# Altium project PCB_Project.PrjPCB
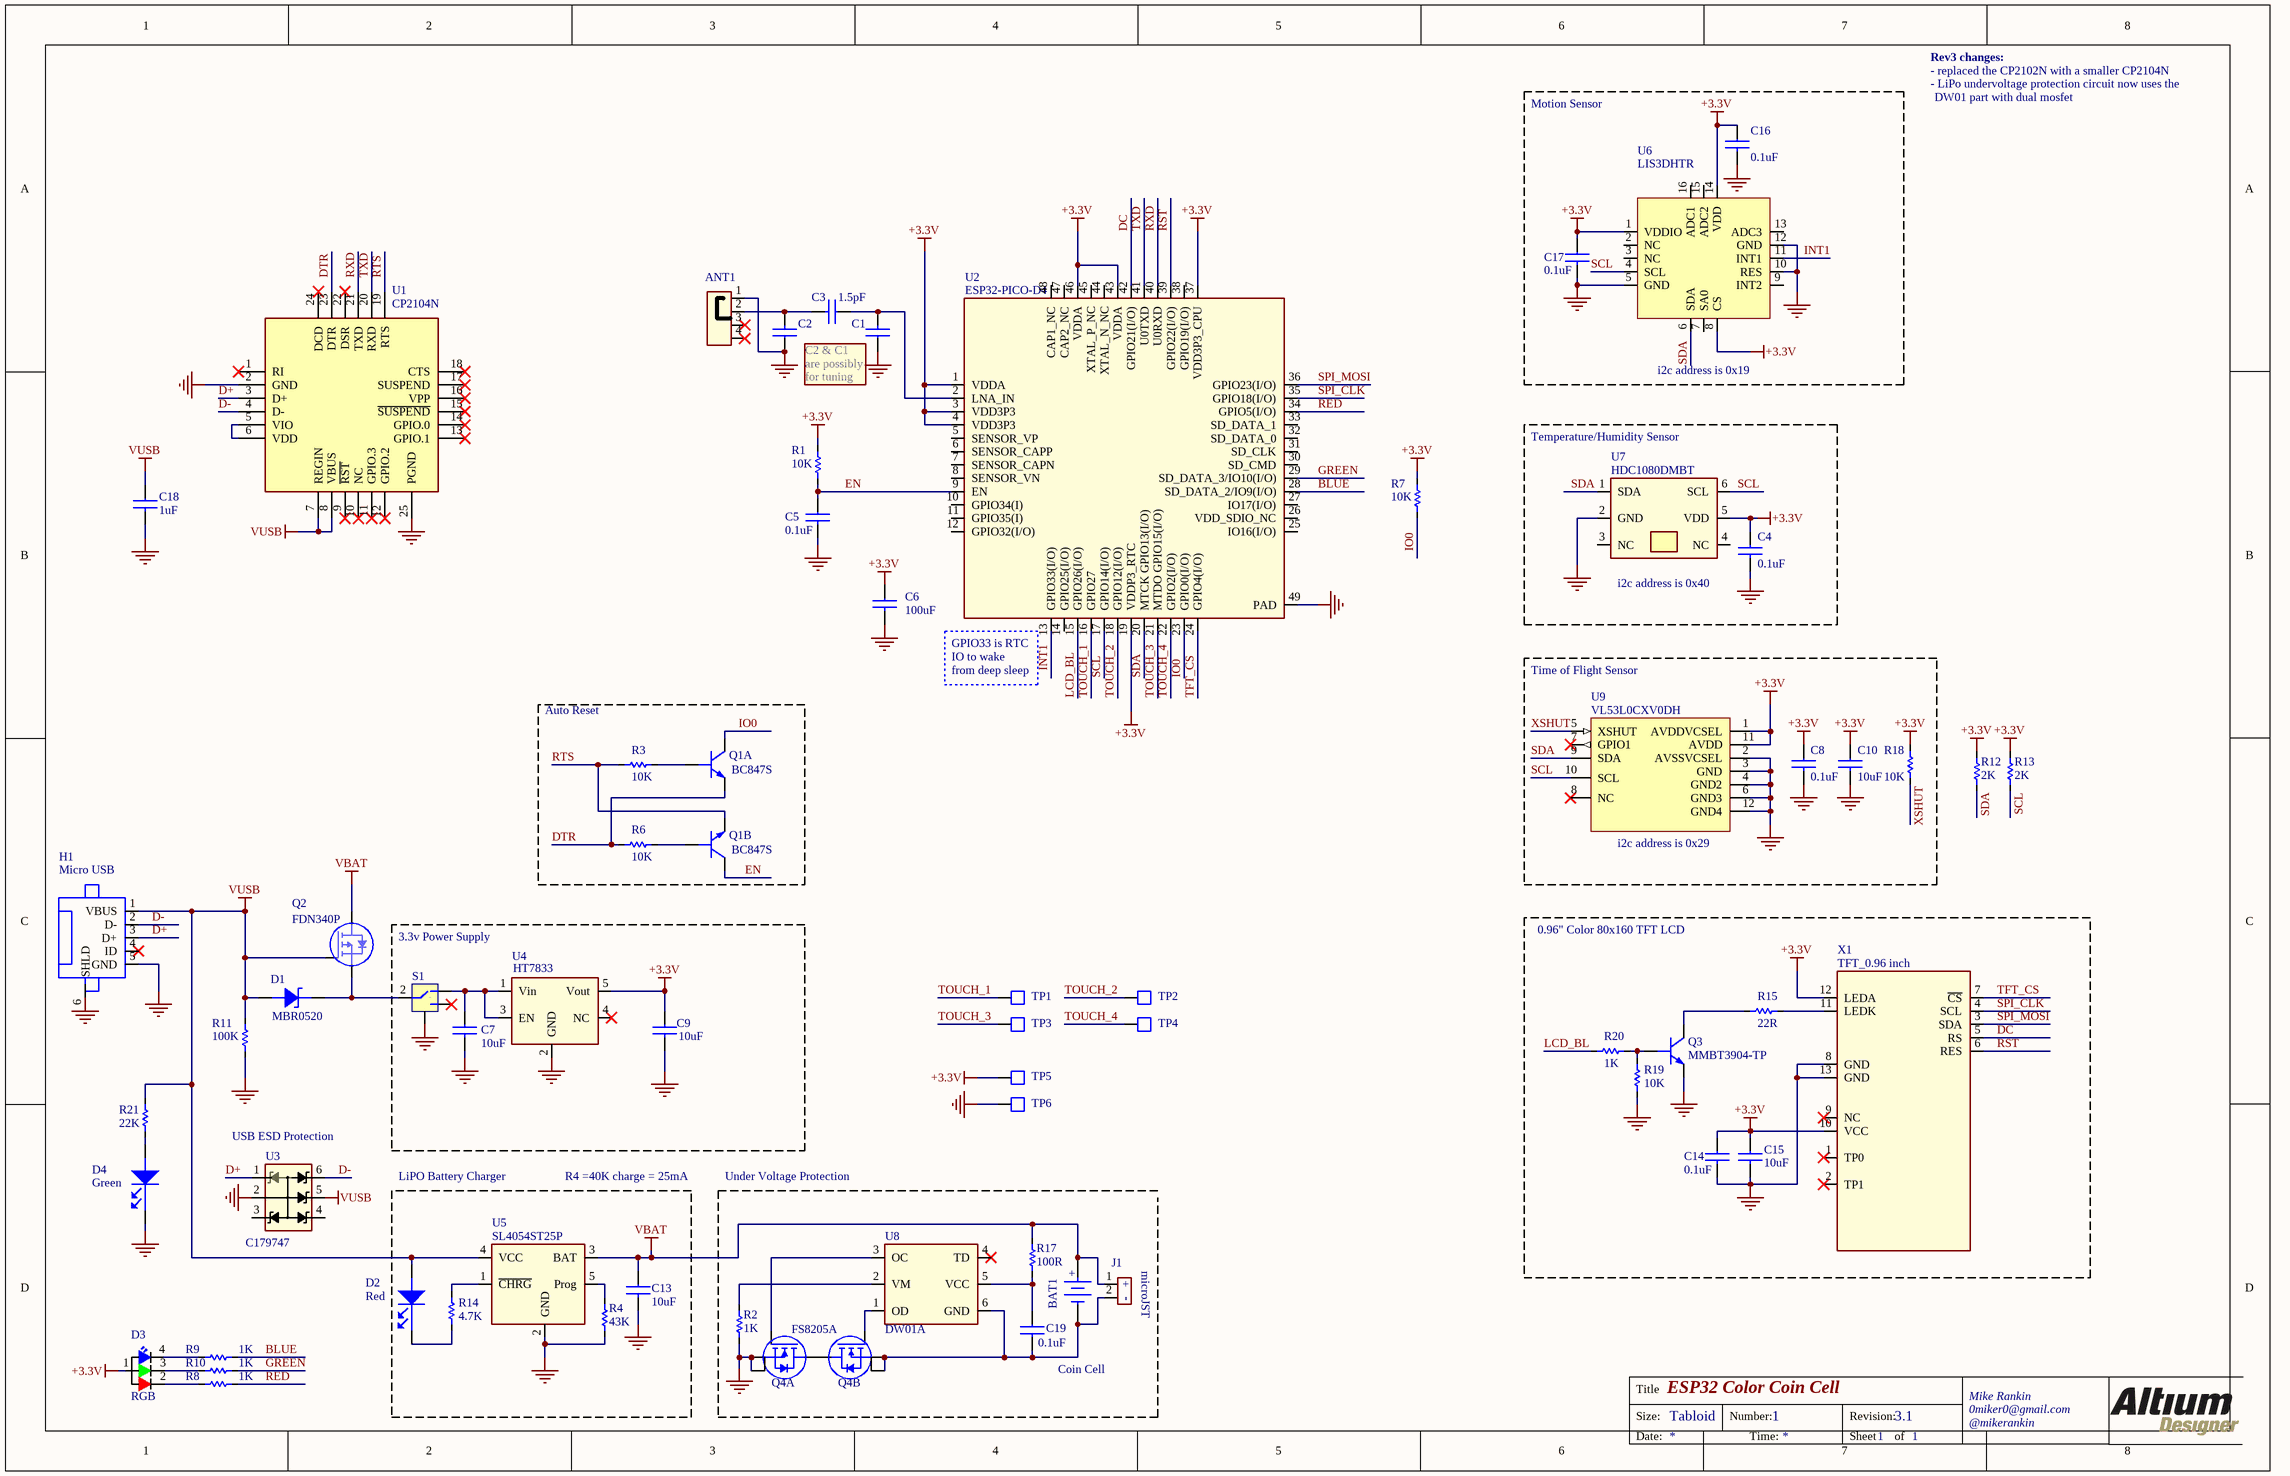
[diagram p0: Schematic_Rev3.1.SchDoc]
1 sheet, 65 parts. Net scope: global (net labels, ports and power ports of the same name join across sheets).
Board file: PCB_Rev3.1.PcbDoc

## Sheet Schematic_Rev3.1.SchDoc: ESP32 Color Coin Cell
size Tabloid; DrawnBy: x; Engineer: x; Address1: Mike Rankin; Address2: 0miker0@gmail.com; Address3: @mikerankin; DocumentNumber: 1; Revision: 3.1; SheetNumber: 1; SheetTotal: 1

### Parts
ANT1  RF ANT 2.4GHZ STAMPED MET SLD  [PRO-OB-440]  (value not drawn)
BAT1  BATTERY-HOLDER (2450)  [BU2450SM-JJ-GTR]  (value not drawn)
C1  (no value)  [CAPC1005X56N]  (no BOM)
C2  (no value)  [CAPC1005X56N]  (no BOM)
C3  1.5pF  [CAPC1005X56N]
C4  0.1uF  [CAPC1005X56N]
C5  0.1uF  [CAPC1005X56N]
C6  100uF  [CAPC3216X160L]
C7  10uF  [CAPC2012X140N]
C8  0.1uF  [CAPC1005X56N]
C9  10uF  [CAPC2012X140N]
C10  10uF  [CAPC2012X140N]
C13  10uF  [CAPC2012X140N]
C14  0.1uF  [CAPC1005X56N]
C15  10uF  [CAPC2012X140N]
C16  0.1uF  [RESC1005X40L]
C17  0.1uF  [CAPC1005X56N]
C18  1uF  [CAPC1005X56N]
C19  0.1uF  [CAPC1005X56N]
D1  MBR0520  [SOD123]
D2  value Red  [LED1608X55N-RED]  (hidden comment: LED_0603)
D3  RGB  [FC-B1010RGBT-HG]
D4  value Green  [LED1608X55N-GREEN]  (hidden comment: LED_0603)
H1  Micro USB  [1981584-1]
J1  CON2  [JST_Micro_2PIN]  (value not drawn)  (no BOM)
Q1  BC847S  [SOT65P210X110-6N]  (parts A,B of 2)
Q2  FDN340P  [SOT95P240X110-3N]
Q3  MMBT3904-TP  [SOT95P240X110-3N]
Q4  FS8205A  [TSOP65P490X110-8N WIDE]  (value not drawn)  (parts A,B of 2)
R1  10K  [RESC1005X40L]
R2  1K  [RESC1005X40L]
R3  10K  [RESC1005X40L]
R4  43K  [RESC1005X40L]
R6  10K  [RESC1005X40L]
R7  10K  [RESC1005X40L]
R8  1K  [RESC1005X40L]
R9  1K  [RESC1005X40L]
R10  1K  [RESC1005X40L]
R11  100K  [RESC1005X40L]
R12  2K  [RESC1005X40L]
R13  2K  [RESC1005X40L]
R14  4.7K  [RESC1005X40L]
R15  22R  [RESC1005X40L]
R17  100R  [RESC1005X40L]
R18  10K  [RESC1005X40L]
R19  10K  [RESC1005X40L]
R20  1K  [RESC1005X40L]
R21  22K  [RESC1005X40L]
S1  SWITCH SLIDE  [K3-1296S-E1]  (value not drawn)
TP1  Test Point, 1mm Top Layer  [TP100TL]  (value not drawn)  (no BOM)
TP2  Test Point, 1mm Top Layer  [TP100TL]  (value not drawn)  (no BOM)
TP3  Test Point, 1mm Top Layer  [TP100TL]  (value not drawn)  (no BOM)
TP4  Test Point, 1mm Top Layer  [TP100TL]  (value not drawn)  (no BOM)
TP5  Test Point, 1mm Top Layer  [TP100TL]  (value not drawn)  (no BOM)
TP6  Test Point, 1mm Top Layer  [TP100TL]  (value not drawn)  (no BOM)
U1  CP2104N  [24-QFN]
U2  ESP32-PICO-D4  [QFN48]
U3  PartNumber: C179747  [SOT65P210X110-6N]  (hidden comment: PESD5V0L5UY)
U4  HT7833  [SOT95P280X144-5N]
U5  SL4054ST25P  [SOT95P280X144-5N]
U6  LIS3DHTR  [QFN3X3_16_1.2]
U7  HDC1080DMBT  [HDC1080]
U8  DW01A  [SOT95P280X130-6N]
U9  VL53L0CXV0DH  [VL53L0CXV0DH]
X1  TFT_0.96 inch  [TFT_GLASS 0.96 INCH]

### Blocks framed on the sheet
Auto Reset: Q1 R3 R6
3.3v Power Supply: C7 C9 S1 U4
0.96" Color 80x160 TFT LCD: C14 C15 Q3 R15 R19 R20 X1

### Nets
+3.3V: C4.1 C6.1 C8.1 C9.1 C10.1 C14.1 C15.1 C16.1 C17.1 D3.1 R1.1 R7.1 R12.2 R13.2 R18.1 TP5.1 U2.1(VDDA) U2.3(VDD3P3) U2.4(VDD3P3) U2.19(VDDP3_RTC) U2.37(VDD3P3_CPU) U2.43(VDDA) U2.46(VDDA) U4.5(Vout) U6.1(VDDIO) U6.8(CS) U6.14(VDD) U7.5(VDD) U9.1(AVDDVCSEL) U9.11(AVDD) X1.10(VCC) X1.12(LEDA)
GND: ANT1.1 C1.1 C2.1 C4.2 C5.2 C6.2 C7.2 C8.2 C9.2 C10.2 C13.2 C14.2 C15.2 C16.2 C17.2 C18.2 D4.1(CATHODE) H1.5(GND) H1.6(SHLD) Q3.2(E) Q4.2(S) Q4.3(S) R2.1 R4.2 R11.2 R19.2 S1.4 TP6.1 U1.2(GND) U1.25(PGND) U2.49(PAD) U3.2 U4.2(GND) U5.2(GND) U6.5(GND) U6.10(RES) U6.12(GND) U7.2(GND) U9.2(AVSSVCSEL) U9.3(GND) U9.4(GND2) U9.6(GND3) U9.12(GND4) X1.8(GND) X1.13(GND)
VBAT: BAT1.1(+) C13.1 J1.1 Q2.3(D) R17.2 U5.3(BAT)
VUSB: C18.1 D1.2(Annode) D2.2(ANODE) H1.1(VBUS) Q2.1(G) R11.1 R21.2 U1.7(REGIN) U1.8(VBUS) U3.5 U5.4(VCC)
BLUE: R9.2 U2.28(SD_DATA_2/IO9(I/O))
D+: H1.3(D+) U1.3(D+) U3.1
D-: H1.2(D-) U1.4(D-) U3.6
DC: U2.42(GPIO21(I/O)) X1.5(RS)
DTR: Q1.1(E1) R6.2 U1.23(DTR)
EN: C5.1 Q1.3(C2) R1.2 U2.9(EN)
GREEN: R10.2 U2.29(SD_DATA_3/IO10(I/O))
INT1: U2.13(GPIO33(I/O)) U6.11(INT1)
IO0: Q1.6(C1) R7.2 U2.23(GPIO0(I/O))
LCD_BL: R20.1 U2.15(GPIO26(I/O))
RED: R8.2 U2.34(GPIO5(I/O))
RST: U2.39(GPIO22(I/O)) X1.6(RES)
RTS: Q1.4(E2) R3.2 U1.19(RTS)
RXD: U1.21(TXD) U2.40(U0RXD)
SCL: R13.1 U2.17(GPIO14(I/O)) U6.4(SCL) U7.6(SCL) U9.10(SCL)
SDA: R12.1 U2.20(MTCK_GPIO13(I/O)) U6.6(SDA) U7.1(SDA) U9.9(SDA)
SPI_CLK: U2.35(GPIO18(I/O)) X1.4(SCL)
SPI_MOSI: U2.36(GPIO23(I/O)) X1.3(SDA)
TFT_CS: U2.24(GPIO4(I/O)) X1.7(~{CS})
TOUCH_1: TP1.1 U2.16(GPIO27)
TOUCH_2: TP2.1 U2.18(GPIO12(I/O))
TOUCH_3: TP3.1 U2.21(MTDO_GPIO15(I/O))
TOUCH_4: TP4.1 U2.22(GPIO2(I/O))
TXD: U1.20(RXD) U2.41(U0TXD)
XSHUT: R18.2 U9.5(XSHUT)
NetANT1_2: ANT1.2 C2.2 C3.2
NetBAT1_2: BAT1.2(-) C19.2 J1.2 Q4.6(S) Q4.7(S) U8.6(GND)
NetC1_2: C1.2 C3.1 U2.2(LNA_IN)
NetC7_1: C7.1 S1.1 U4.1(Vin) U4.3(EN)
NetC19_1: C19.1 R17.1 U8.5(VCC)
NetD1_1: D1.1(Cathode) Q2.2(S) S1.2
NetD2_1: D2.1(CATHODE) R14.1
NetD3_2: D3.2 R8.1
NetD3_3: D3.3 R10.1
NetD3_4: D3.4 R9.1
NetD4_2: D4.2(ANODE) R21.1
NetQ1_2: Q1.2(B1) R3.1
NetQ1_5: Q1.5(B2) R6.1
NetQ3_1: Q3.1(B) R19.1 R20.2
NetQ3_3: Q3.3(C) R15.2
NetQ4_1: Q4.1(D) Q4.8(D)
NetQ4_4: Q4.4(G) U8.3(OC)
NetQ4_5: Q4.5(G) U8.1(OD)
NetR2_2: R2.2 U8.2(VM)
NetR4_1: R4.1 U5.5(Prog)
NetR14_2: R14.2 U5.1(~{CHRG})
NetR15_1: R15.1 X1.11(LEDK)
NetU1_5: U1.5(VIO) U1.6(VDD)

Not connected (* = marked no-connect by the designer): ANT1 3* 4*; H1 4(ID)*; S1 3*; U1 1(RI)* 9(~{RST})* 10(NC)* 11(GPIO.3)* 12(GPIO.2)* 13(GPIO.1)* 14(GPIO.0)* 15(~{SUSPEND})* 16(VPP)* 17(SUSPEND)* 18(CTS)* 22(DSR)* 24(DCD)*; U2 5(SENSOR_VP) 6(SENSOR_CAPP) 7(SENSOR_CAPN) 8(SENSOR_VN) 10(GPIO34(I)) 11(GPIO35(I)) 12(GPIO32(I/O)) 14(GPIO25(I/O)) 25(IO16(I/O)) 26(VDD_SDIO_NC) 27(IO17(I/O)) 30(SD_CMD) 31(SD_CLK) 32(SD_DATA_0) 33(SD_DATA_1) 38(GPIO19(I/O)) 44(XTAL_N_NC) 45(XTAL_P_NC) 47(CAP2_NC) 48(CAP1_NC); U3 3 4; U4 4(NC)*; U6 2(NC) 3(NC) 7(SA0) 9(INT2) 13(ADC3) 15(ADC2) 16(ADC1); U7 3(NC) 4(NC); U8 4(TD)*; U9 7(GPIO1)* 8(NC)*; X1 1(TP0)* 2(TP1)* 9(NC)*

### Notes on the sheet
- Rev3 changes:
- - replaced the CP2102N with a smaller CP2104N
- - LiPo undervoltage protection circuit now uses the
- Motion Sensor
- DW01 part with dual mosfet
- C2 & C1
- are possibly
- for tuning
- (near U6) i2c address is 0x19
- (near U7) Temperature/Humidity Sensor
- i2c address is 0x40
- (near U2) GPIO33 is RTC
- (near U2) IO to wake
- (near U2) from deep sleep
- Time of Flight Sensor
- (near U9) i2c address is 0x29
- (near U3) USB ESD Protection
- LiPO Battery Charger
- R4 =40K charge = 25mA
- Under Voltage Protection
- (near J1) microJST
- (near C19) Coin Cell
- Labels drawn without touching a wire or pin: ~{}

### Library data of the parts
ANT1 = PRO-OB-440: Manufacturer: Proant AB; Vendor: Digi-Key
BAT1 = BU2450SM-JJ-GTR: HOLDER,BATT,COIN,24.5MM,SMT; Manufacturer: MPD; Value: Coin Cell Holder; Vendor: Digi-Key
C1 C2 = CAP_0402: DNP
C3 = CAP_0402: CAP 1.5pF 0402; PartNumber: C147344; Manufacturer: Dafron; Part_Footprint: 0402; Vendor: LCSC
C4 C5 C8 C14 C16 C17 C19 = CAP_0402: CAP 0.1uF 0402; PartNumber: C344190; Manufacturer: CCTC; Vendor: LCSC
C6 = CAP_1206: CAP 100uF 6.3V 1206; PartNumber: C87164; Manufacturer: Taiyo Yuden; Vendor: LCSC
C7 C9 C10 C15 = CAP_0805: CAP 10uF 0805; Manufacturer: Samsung; PartNumber: C307520; Vendor: LCSC
C13 = CAP_0805: CAP 10uF 0805; PartNumber: C307520; Manufacturer: Samsung; Vendor: LCSC
C18 = CAP_0603: CAP 1uF 16V 0402; PartNumber: C83063; Manufacturer: Walsin; Vendor: LCSC
D1 = MBR0520-TP: DIODE SCHOTTKY 20V 500MA SOD123; Manufacturer: CJ; PartNumber: C475717; Vendor: LCSC
D2 = LED_0603: LED RED CLEAR 0603 SMD; Manufacturer: FNO; PartNumber: C94869; Vendor: LCSC
D3 = FC-B1010RGBT-HG: LED,RGB LED,SMD,RoHS; PartNumber: C158099; Manufacturer: Foshan; Vendor: LCSC; Value: RGB Led
D4 = LED_0603: LED Green 0603; Manufacturer: Lite-On; PartNumber: C125094; Vendor: LCSC
H1 = 1981584-1: CONN RCPT MICRO USB TYPE AB; Manufacturer: REG CON; PartNumber: C21377; Vendor: LCSC
J1 = JST_Micro_CONN_2PIN: JST MIcro CONN 2POS
Q1 = BC847S: TRANS 2NPN 44V 0.1A SC-70-6; Manufacturer: Changjiang; Vendor: LCSC
Q2 = FDN340P: MOSFET P-CH 20V 2A SOT-23; Manufacturer: On Semi; PartNumber: C75469; Vendor: LCSC; Value: Mosfet P-H
Q3 = MMBT3904-TP: TRANSISTOR NPN SOT23; Manufacturer: Micro Commercial; PartNumber: C668969; Vendor: LCSC
Q4 = FS8205A: MOSFET 2N-CH 20V 6A TSSOP-8L; Manufacturer: Fortune; PartNumber: C16052; Vendor: LCSC
R1 R3 R6 R7 R18 R19 = RES_0402: RES 10K 0402; PartNumber: C258091; Manufacturer: Guangdong; Vendor: LCSC
R2 R8-R10 R20 = RES_0402: RES 1K 0402; PartNumber: C106235; Manufacturer: Yageo; Vendor: LCSC
R4 = RES_0603: RES 43K 0402; Manufacturer: Uniroyal; PartNumber: C8329; Vendor: LCSC
R11 = RES_0603: RES 100K 0402; Manufacturer: Uniroyal Elec; PartNumber: C25741; Vendor: LCSC
R12 R13 = RES_0402: RES 2K 0402; Manufacturer: LIZ Elec; PartNumber: C100291; Vendor: LCSC
R14 = RES_0603: RES 4.7K 0402; Manufacturer: LIZ Elec; PartNumber: C100139; Vendor: LCSC
R15 = RES_0402: RES 22R 0402; PartNumber: C25092; Manufacturer: Uniroyal; Vendor: LCSC
R17 = RES_0603: RES 100R 0402; Manufacturer: Yageo; PartNumber: C106232; Vendor: LCSC
R21 = RES_0603: RES 22K 0402; Manufacturer: LIZ Elec; PartNumber: C100310; Vendor: LCSC
S1 = K3-1296S-E1: SWITCH SLIDE SMD; Manufacturer: Korean Hroparts Elec; PartNumber: C128955; Vendor: LCSC
U1 = CP2104N: IC BRIDGE USB TO UART 24QFN; Manufacturer: Silicon Labs; PartNumber: C47742; Vendor: LCSC
U2 = ESP32-PICO-D4: RF Transceiver ICs QFN-48_7x7x05P RoHS; Manufacturer: Espressif; PartNumber: C193707; Vendor: LCSC
U3 = PESD5V0L5UY: TVS SOT-363 RoHS; Manufacturer: Yenji; Vendor: LCSC
U4 = HT7833: IC LDO 3.3V 0.5A SOT23-5; Manufacturer: Holtek; PartNumber: C164106; Vendor: LCSC
U5 = SL4054ST25P: Charger IC Lithium-Ion/Polymer SOT23-5; Manufacturer: Techfuse; PartNumber: C258510; Vendor: LCSC
U6 = E-05-177: IC ACCEL 2-16G I2C/SPI 16LGA; PartNumber: C15134; Manufacturer: STMicro; Vendor: LCSC
U7 = HDC1080DMBT: Humidity/Temperature Sensor; Manufacturer: Texas Instruments; PartNumber: C82227; Vendor: LCSC
U8 = DW01A: IC LITHIUM BATT PROTECT SOT-23-6L; Manufacturer: PUOLOP; PartNumber: C351410; Vendor: LCSC
U9 = VL53L0CXV0DH: LASER SENSOR; Manufacturer: ST MICRO; PartNumber: C91199; Value: VL53L0CXV0DH/1; Vendor: LCSC
X1 = TFT_GLASS 0.96 INCH COLOR: 0.96 INCH TFT GLASS COLOR; PartNumber: ER-TFT0.96-1; Manufacturer: BuyDisplay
